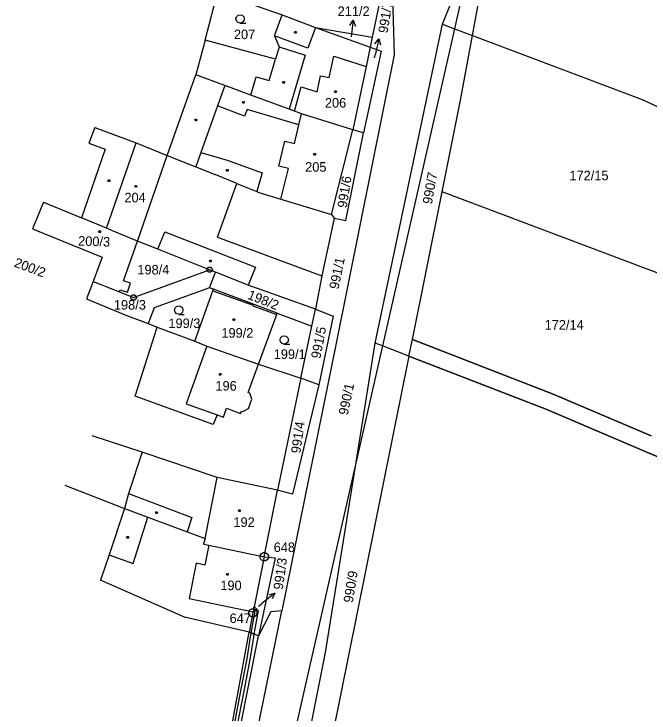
# Model space of a CAD drawing. Extents: x -755359 to -754474, y -1162585 to -1161655.
# Drawn here: x -755100.2 to -754987.3, y -1161900.8 to -1161776.6 of the extents above; entities that cross this region are included whole.
import ezdxf

# ---------------------------------------------------------------- set-up
doc = ezdxf.new("R2010")
doc.units = 0
for name, color, linetype in [('Vrstva 1', 7, 'Continuous'), ('Vrstva 12', 7, 'Continuous'), ('Vrstva 13', 7, 'Continuous'), ('Vrstva 2', 7, 'Continuous'), ('Vrstva 3', 7, 'Continuous'), ('Vrstva 4', 7, 'Continuous'), ('Vrstva 5', 7, 'Continuous'), ('Vrstva 7', 7, 'Continuous'), ('Vrstva 8', 7, 'Continuous')]:
    doc.layers.add(name, color=color, linetype=linetype)

msp = doc.modelspace()

# ---------------------------------------------------------------- linework, layer by layer
at = {"layer": 'Vrstva 1'}
for p, q in [((-755018.69, -1161780.44), (-755012.38, -1161745.91)), ((-755029.37, -1161746.66), (-755036.5, -1161780.73)), ((-755023.99, -1161778.44), (-755018.66, -1161765.05)), ((-755032.94, -1161771.83), (-755032.59, -1161783.86)), ((-755066.23, -1161781.24), (-755063.99, -1161772.75)), ((-755063.99, -1161772.75), (-755052.51, -1161776.75)), ((-755053.85, -1161780.46), (-755052.51, -1161776.75)), ((-755052.51, -1161776.75), (-755046.56, -1161779)), ((-755035.96, -1161835.09), (-755023.99, -1161778.44)), ((-755023.99, -1161778.44), (-755021.88, -1161779.23)), ((-755046.56, -1161779), (-755036.5, -1161780.73)), ((-755046.56, -1161779), (-755036.87, -1161782.52)), ((-755021.88, -1161779.23), (-755018.69, -1161780.44)), ((-755066.23, -1161781.24), (-755067.86, -1161787.41)), ((-755053.71, -1161784.66), (-755066.23, -1161781.24)), ((-755053.85, -1161780.46), (-755053.05, -1161782.42)), ((-755036.5, -1161780.73), (-755036.87, -1161782.52)), ((-755020.78, -1161791.91), (-755018.69, -1161780.44)), ((-755018.69, -1161780.44), (-754988.48, -1161791.81)), ((-755053.05, -1161782.42), (-755053.71, -1161784.66)), ((-755036.87, -1161782.52), (-755037.58, -1161785.91)), ((-755036.87, -1161782.52), (-755034.91, -1161783.19)), ((-755032.59, -1161783.86), (-755042.91, -1161835.1)), ((-755034.91, -1161783.19), (-755038.07, -1161797.72)), ((-755037.58, -1161785.91), (-755039.95, -1161797.18)), ((-755072.94, -1161801.75), (-755067.86, -1161787.41)), ((-755062.7, -1161789.31), (-755067.86, -1161787.41)), ((-755067.86, -1161787.41), (-755067.86, -1161787.41)), ((-755058.07, -1161791.01), (-755062.7, -1161789.31)), ((-755051.25, -1161793.52), (-755058.07, -1161791.01)), ((-755024.07, -1161808.23), (-755020.78, -1161791.91)), ((-754988.48, -1161791.81), (-754976.02, -1161797.59)), ((-755050.33, -1161793.86), (-755051.25, -1161793.52)), ((-755049.05, -1161794.33), (-755050.33, -1161793.86)), ((-755039.95, -1161797.18), (-755049.05, -1161794.33)), ((-755085.83, -1161796.77), (-755086.86, -1161799.58)), ((-755085.83, -1161796.77), (-755085.83, -1161796.77)), ((-755085.83, -1161796.77), (-755078.48, -1161799.49)), ((-755043.71, -1161812.24), (-755039.95, -1161797.18)), ((-755038.07, -1161797.72), (-755039.95, -1161797.18)), ((-755041.18, -1161813.33), (-755038.07, -1161797.72)), ((-755086.86, -1161799.58), (-755084.01, -1161800.63)), ((-755078.48, -1161799.49), (-755072.94, -1161801.75)), ((-755084.01, -1161800.63), (-755088.17, -1161812.84)), ((-755072.94, -1161801.75), (-755067.84, -1161803.8)), ((-755067.84, -1161803.8), (-755064.4, -1161805.16)), ((-755060.56, -1161806.72), (-755064.4, -1161805.16)), ((-755064, -1161816.28), (-755060.56, -1161806.72)), ((-755024.25, -1161809.12), (-755024.07, -1161808.23)), ((-754981.41, -1161824.3), (-755024.07, -1161808.23)), ((-755029.36, -1161834.44), (-755024.25, -1161809.12)), ((-755094.97, -1161810.07), (-755096.9, -1161814.81)), ((-755094.97, -1161810.07), (-755094.97, -1161810.07)), ((-755094.97, -1161810.07), (-755088.17, -1161812.84)), ((-755043.71, -1161812.24), (-755043.26, -1161812.92)), ((-755083.75, -1161814.68), (-755088.17, -1161812.84)), ((-755043.26, -1161812.92), (-755045.44, -1161823.16)), ((-755043.26, -1161812.92), (-755041.18, -1161813.33)), ((-755096.9, -1161814.81), (-755084.49, -1161819.84)), ((-755082.7, -1161815.12), (-755083.75, -1161814.68)), ((-755078.25, -1161816.98), (-755082.7, -1161815.12)), ((-755080.73, -1161824.02), (-755078.25, -1161816.98)), ((-755074.63, -1161818.41), (-755078.25, -1161816.98)), ((-755064, -1161816.28), (-755045.44, -1161823.16)), ((-755065.41, -1161822.06), (-755074.63, -1161818.41)), ((-755084.49, -1161819.84), (-755086.12, -1161824.14)), ((-755078.92, -1161826.99), (-755065.41, -1161822.06)), ((-755064.35, -1161822.48), (-755065.41, -1161822.06)), ((-755065.45, -1161825.27), (-755064.35, -1161822.48)), ((-755058.54, -1161824.78), (-755064.35, -1161822.48)), ((-755045.44, -1161823.16), (-755046.61, -1161829.09)), ((-755086.12, -1161824.14), (-755087.3, -1161827.26)), ((-755086.12, -1161824.14), (-755086.12, -1161824.14)), ((-755086.12, -1161824.14), (-755081.43, -1161826)), ((-755079.47, -1161824.46), (-755080.73, -1161824.02)), ((-755080, -1161826.07), (-755079.47, -1161824.46)), ((-755046.61, -1161829.09), (-755058.54, -1161824.78)), ((-755081.43, -1161826), (-755081.29, -1161825.61)), ((-755081.43, -1161826), (-755078.92, -1161826.99)), ((-755081.29, -1161825.61), (-755080, -1161826.07)), ((-755065.45, -1161825.27), (-755075.27, -1161828.85)), ((-755068.04, -1161834.73), (-755064.84, -1161825.82)), ((-755064.74, -1161825.54), (-755065.45, -1161825.27)), ((-755064.84, -1161825.82), (-755064.74, -1161825.54)), ((-755053.39, -1161829.8), (-755064.74, -1161825.54)), ((-755087.3, -1161827.26), (-755080.31, -1161830.13)), ((-755087.3, -1161827.26), (-755087.3, -1161827.26)), ((-755075.27, -1161828.85), (-755076.34, -1161831.64)), ((-755053.47, -1161830.02), (-755053.39, -1161829.8)), ((-755053.39, -1161829.8), (-755047.24, -1161832.11)), ((-755047.24, -1161832.11), (-755046.61, -1161829.09)), ((-755046.61, -1161829.09), (-755043.45, -1161830.32)), ((-755080.31, -1161830.13), (-755076.34, -1161831.64)), ((-755056.74, -1161838.86), (-755053.47, -1161830.02)), ((-755043.45, -1161830.32), (-755046.01, -1161842.53)), ((-755078.65, -1161844.52), (-755074.72, -1161832.26)), ((-755076.34, -1161831.64), (-755074.72, -1161832.26)), ((-755074.72, -1161832.26), (-755068.04, -1161834.73)), ((-755049.18, -1161841.35), (-755047.24, -1161832.11)), ((-755068.04, -1161834.73), (-755065.91, -1161835.63)), ((-755029.96, -1161837.42), (-755029.36, -1161834.44)), ((-755004.33, -1161844.15), (-755029.36, -1161834.44)), ((-755065.91, -1161835.63), (-755056.74, -1161838.86)), ((-755042.91, -1161835.1), (-755052.57, -1161882.7)), ((-755039.31, -1161855.89), (-755035.96, -1161835.09)), ((-755034.69, -1161835.58), (-755035.96, -1161835.09)), ((-755029.96, -1161837.42), (-755034.69, -1161835.58)), ((-755029.96, -1161837.42), (-755040.69, -1161890.6)), ((-755029.96, -1161837.42), (-755005.46, -1161846.93)), ((-755058.56, -1161843.89), (-755056.74, -1161838.86)), ((-755056.74, -1161838.86), (-755049.18, -1161841.35)), ((-755049.18, -1161841.35), (-755053.32, -1161861.22)), ((-755046.01, -1161842.53), (-755049.18, -1161841.35)), ((-755046.01, -1161842.53), (-755050.67, -1161861.93)), ((-755064.76, -1161849.59), (-755078.65, -1161844.52)), ((-755058.26, -1161844), (-755058.56, -1161843.89)), ((-755057.9, -1161845.09), (-755058.26, -1161844)), ((-754986.91, -1161851.57), (-755004.33, -1161844.15)), ((-755058.48, -1161846.72), (-755057.9, -1161845.09)), ((-755062.95, -1161848.24), (-755062.42, -1161846.64)), ((-755062.42, -1161846.64), (-755059.89, -1161847.61)), ((-755059.89, -1161847.61), (-755059.74, -1161847.19)), ((-755059.74, -1161847.19), (-755059.5, -1161847.27)), ((-755059.5, -1161847.27), (-755058.48, -1161846.72)), ((-755005.46, -1161846.93), (-754987.52, -1161854.57)), ((-755064.08, -1161847.84), (-755064.76, -1161849.59)), ((-755064.08, -1161847.84), (-755062.95, -1161848.24)), ((-755077.38, -1161854.48), (-755086.27, -1161851.57)), ((-755086.27, -1161851.57), (-755086.27, -1161851.57)), ((-755077.38, -1161854.48), (-755079.84, -1161861.83)), ((-755064.04, -1161858.98), (-755077.38, -1161854.48)), ((-754987.52, -1161854.57), (-754912.51, -1161886.53)), ((-755044.81, -1161890.11), (-755039.31, -1161855.89)), ((-755053.32, -1161861.22), (-755064.04, -1161858.98)), ((-755091.15, -1161860.37), (-755091.15, -1161860.37)), ((-755091.15, -1161860.37), (-755080.57, -1161864.47)), ((-755079.84, -1161861.83), (-755080.57, -1161864.47)), ((-755055.68, -1161873.06), (-755053.32, -1161861.22)), ((-755050.67, -1161861.93), (-755053.32, -1161861.22)), ((-755080.57, -1161864.47), (-755083.3, -1161872.73)), ((-755080.57, -1161864.47), (-755076.39, -1161866.02)), ((-755076.39, -1161866.02), (-755069.39, -1161868.63)), ((-755069.39, -1161868.63), (-755066.22, -1161869.81)), ((-755066.22, -1161869.81), (-755066.47, -1161870.86)), ((-755066.47, -1161870.86), (-755065.57, -1161871.04)), ((-755065.57, -1161871.04), (-755055.68, -1161873.06)), ((-755083.3, -1161872.73), (-755084.79, -1161877.24)), ((-755055.68, -1161873.06), (-755057.66, -1161882.87)), ((-755053.78, -1161873.28), (-755056.71, -1161887.12)), ((-755055.68, -1161873.06), (-755053.78, -1161873.28)), ((-755069.89, -1161883.79), (-755084.79, -1161877.24)), ((-755084.79, -1161877.24), (-755084.79, -1161877.24)), ((-755057.71, -1161883.06), (-755058.39, -1161886.49)), ((-755057.66, -1161882.87), (-755057.71, -1161883.06)), ((-755054.53, -1161882.87), (-755056.71, -1161887.12)), ((-755052.57, -1161882.7), (-755054.53, -1161882.87)), ((-755058.39, -1161886.49), (-755069.89, -1161883.79)), ((-755064.41, -1161919.47), (-755058.39, -1161886.49)), ((-755056.71, -1161887.12), (-755058.39, -1161886.49)), ((-755077.79, -1161993.12), (-755056.71, -1161887.12)), ((-755053.45, -1161933.51), (-755044.81, -1161890.11)), ((-755040.69, -1161890.6), (-755049.81, -1161934.92))]:
    msp.add_line(p, q, dxfattribs=at)
at = {"layer": 'Vrstva 12'}
for p, q in [((-755044.13, -1161787.9), (-755043.32, -1161784.1)), ((-755043.32, -1161784.1), (-755037.58, -1161785.91)), ((-755037.58, -1161785.91), (-755039.95, -1161797.18)), ((-755046.28, -1161790.43), (-755045.67, -1161787.57)), ((-755045.67, -1161787.57), (-755044.13, -1161787.9)), ((-755050.33, -1161793.86), (-755049.11, -1161789.56)), ((-755049.11, -1161789.56), (-755046.28, -1161790.43)), ((-755049.05, -1161794.33), (-755050.33, -1161793.86)), ((-755049.52, -1161796.33), (-755049.05, -1161794.33)), ((-755039.95, -1161797.18), (-755049.05, -1161794.33)), ((-755039.95, -1161797.18), (-755049.05, -1161794.33)), ((-755050.32, -1161799.64), (-755049.52, -1161796.33)), ((-755043.71, -1161812.24), (-755039.95, -1161797.18)), ((-755083.75, -1161814.68), (-755078.48, -1161799.49)), ((-755078.48, -1161799.49), (-755072.94, -1161801.75)), ((-755053.09, -1161803.64), (-755052.02, -1161799.21)), ((-755052.02, -1161799.21), (-755050.32, -1161799.64)), ((-755078.25, -1161816.98), (-755072.94, -1161801.75)), ((-755051.39, -1161804.05), (-755053.09, -1161803.64)), ((-755052.72, -1161809.52), (-755051.39, -1161804.05)), ((-755052.72, -1161809.52), (-755043.71, -1161812.24)), ((-755094.97, -1161810.07), (-755096.9, -1161814.81)), ((-755094.97, -1161810.07), (-755088.17, -1161812.84)), ((-755083.75, -1161814.68), (-755088.17, -1161812.84)), ((-755096.9, -1161814.81), (-755084.49, -1161819.84)), ((-755082.7, -1161815.12), (-755083.75, -1161814.68)), ((-755082.7, -1161815.12), (-755083.75, -1161814.68)), ((-755078.25, -1161816.98), (-755082.7, -1161815.12)), ((-755078.25, -1161816.98), (-755082.7, -1161815.12)), ((-755080.73, -1161824.02), (-755078.25, -1161816.98)), ((-755084.49, -1161819.84), (-755086.12, -1161824.14)), ((-755086.12, -1161824.14), (-755081.43, -1161826)), ((-755079.47, -1161824.46), (-755080.73, -1161824.02)), ((-755080, -1161826.07), (-755079.47, -1161824.46)), ((-755081.43, -1161826), (-755081.29, -1161825.61)), ((-755081.29, -1161825.61), (-755080, -1161826.07)), ((-755068.04, -1161834.73), (-755064.84, -1161825.82)), ((-755064.84, -1161825.82), (-755057.65, -1161828.38)), ((-755057.65, -1161828.38), (-755057.71, -1161828.5)), ((-755057.71, -1161828.5), (-755053.47, -1161830.02)), ((-755056.74, -1161838.86), (-755053.47, -1161830.02)), ((-755068.04, -1161834.73), (-755065.91, -1161835.63)), ((-755065.91, -1161835.63), (-755069.59, -1161845.88)), ((-755065.91, -1161835.63), (-755056.74, -1161838.86)), ((-755065.91, -1161835.63), (-755056.74, -1161838.86)), ((-755058.56, -1161843.89), (-755056.74, -1161838.86)), ((-755058.26, -1161844), (-755058.56, -1161843.89)), ((-755057.9, -1161845.09), (-755058.26, -1161844)), ((-755069.59, -1161845.88), (-755064.08, -1161847.84)), ((-755058.48, -1161846.72), (-755057.9, -1161845.09)), ((-755062.95, -1161848.24), (-755062.42, -1161846.64)), ((-755062.42, -1161846.64), (-755059.89, -1161847.61)), ((-755059.89, -1161847.61), (-755059.74, -1161847.19)), ((-755059.74, -1161847.19), (-755059.5, -1161847.27)), ((-755059.5, -1161847.27), (-755058.48, -1161846.72)), ((-755064.08, -1161847.84), (-755062.95, -1161848.24)), ((-755066.22, -1161869.81), (-755064.04, -1161858.98)), ((-755053.32, -1161861.22), (-755064.04, -1161858.98)), ((-755055.68, -1161873.06), (-755053.32, -1161861.22)), ((-755066.22, -1161869.81), (-755066.47, -1161870.86)), ((-755066.47, -1161870.86), (-755065.57, -1161871.04)), ((-755065.57, -1161871.04), (-755066.27, -1161874.54)), ((-755065.57, -1161871.04), (-755055.68, -1161873.06)), ((-755065.57, -1161871.04), (-755055.68, -1161873.06)), ((-755055.68, -1161873.06), (-755057.66, -1161882.87)), ((-755067.79, -1161874.23), (-755069.06, -1161880.5)), ((-755066.27, -1161874.54), (-755067.79, -1161874.23)), ((-755069.06, -1161880.5), (-755057.66, -1161882.87))]:
    msp.add_line(p, q, dxfattribs=at)
at = {"layer": 'Vrstva 13'}
for p, q in [((-755029.96, -1161837.42), (-755029.36, -1161834.44)), ((-755029.36, -1161834.44), (-755004.33, -1161844.15)), ((-755005.46, -1161846.93), (-755029.96, -1161837.42)), ((-755004.33, -1161844.15), (-754986.91, -1161851.57)), ((-754987.52, -1161854.57), (-755005.46, -1161846.93)), ((-754956.94, -1161867.6), (-754987.52, -1161854.57)), ((-755057.58, -1161882.48), (-755057.46, -1161881.89)), ((-755057.46, -1161881.89), (-755056.77, -1161882.61)), ((-755058.01, -1161886.63), (-755057.31, -1161882.77)), ((-755057.31, -1161882.77), (-755057.58, -1161882.48)), ((-755056.77, -1161882.61), (-755057.53, -1161886.81)), ((-755058.13, -1161887.3), (-755058.01, -1161886.63)), ((-755058.01, -1161886.63), (-755057.53, -1161886.81)), ((-755057.53, -1161886.81), (-755058.01, -1161886.63)), ((-755057.53, -1161886.81), (-755057.63, -1161887.38)), ((-755058.73, -1161891.23), (-755058.13, -1161887.3)), ((-755057.63, -1161887.38), (-755058.23, -1161891.31)), ((-755059.85, -1161896.89), (-755058.73, -1161891.23)), ((-755058.23, -1161891.31), (-755059.35, -1161896.99)), ((-755061.53, -1161905.62), (-755059.85, -1161896.89)), ((-755059.35, -1161896.99), (-755061.05, -1161905.72))]:
    msp.add_line(p, q, dxfattribs=at)
at = {"layer": 'Vrstva 3'}
for points in [[(-755059.97, -1161778.22), (-755060.35, -1161778.12), (-755060.62, -1161777.85), (-755060.72, -1161777.48), (-755060.62, -1161777.11), (-755060.35, -1161776.84), (-755059.98, -1161776.74), (-755059.61, -1161776.84), (-755059.34, -1161777.11), (-755059.24, -1161777.49), (-755059.34, -1161777.87), (-755059.61, -1161778.14), (-755059.99, -1161778.24), (-755058.99, -1161778.24)], [(-755070.89, -1161829.97), (-755071.27, -1161829.87), (-755071.54, -1161829.6), (-755071.64, -1161829.23), (-755071.54, -1161828.86), (-755071.27, -1161828.59), (-755070.9, -1161828.49), (-755070.53, -1161828.59), (-755070.26, -1161828.86), (-755070.16, -1161829.24), (-755070.26, -1161829.62), (-755070.53, -1161829.89), (-755070.91, -1161829.99), (-755069.91, -1161829.99)], [(-755052.13, -1161835.27), (-755052.51, -1161835.17), (-755052.78, -1161834.9), (-755052.88, -1161834.53), (-755052.78, -1161834.16), (-755052.51, -1161833.89), (-755052.14, -1161833.79), (-755051.77, -1161833.89), (-755051.5, -1161834.16), (-755051.4, -1161834.54), (-755051.5, -1161834.92), (-755051.77, -1161835.19), (-755052.15, -1161835.29), (-755051.15, -1161835.29)]]:
    msp.add_lwpolyline(points, dxfattribs=at)
at = {"layer": 'Vrstva 4'}
for p, q in [((-755018.66, -1161765.05), (-755021.88, -1161779.23)), ((-755046.56, -1161779), (-755047.94, -1161782.68)), ((-755021.88, -1161779.23), (-755034.69, -1161835.58)), ((-755047.94, -1161782.68), (-755053.85, -1161780.46)), ((-755053.05, -1161782.42), (-755048.44, -1161783.92)), ((-755054.84, -1161788.43), (-755053.71, -1161784.66)), ((-755048.44, -1161783.92), (-755051.25, -1161793.52)), ((-755044.13, -1161787.9), (-755043.32, -1161784.1)), ((-755043.32, -1161784.1), (-755037.58, -1161785.91)), ((-755046.28, -1161790.43), (-755045.67, -1161787.57)), ((-755045.67, -1161787.57), (-755044.13, -1161787.9)), ((-755058.07, -1161791.01), (-755057.11, -1161787.75)), ((-755057.11, -1161787.75), (-755054.84, -1161788.43)), ((-755062.7, -1161789.31), (-755064.01, -1161792.95)), ((-755050.33, -1161793.86), (-755049.11, -1161789.56)), ((-755049.11, -1161789.56), (-755046.28, -1161790.43)), ((-755064.01, -1161792.95), (-755066.99, -1161801.2)), ((-755059.19, -1161794.76), (-755064.01, -1161792.95)), ((-755058.74, -1161793.58), (-755059.19, -1161794.76)), ((-755049.52, -1161796.33), (-755058.74, -1161793.58)), ((-755049.52, -1161796.33), (-755049.05, -1161794.33)), ((-755050.32, -1161799.64), (-755049.52, -1161796.33)), ((-755083.75, -1161814.68), (-755078.48, -1161799.49)), ((-755053.09, -1161803.64), (-755052.02, -1161799.21)), ((-755052.02, -1161799.21), (-755050.32, -1161799.64)), ((-755066.99, -1161801.2), (-755067.84, -1161803.8)), ((-755066.99, -1161801.2), (-755062.31, -1161802.61)), ((-755078.25, -1161816.98), (-755072.94, -1161801.75)), ((-755062.31, -1161802.61), (-755056.07, -1161804.84)), ((-755051.39, -1161804.05), (-755053.09, -1161803.64)), ((-755056.07, -1161804.84), (-755056.99, -1161808.17)), ((-755052.72, -1161809.52), (-755051.39, -1161804.05)), ((-755060.56, -1161806.72), (-755056.99, -1161808.17)), ((-755056.99, -1161808.17), (-755056.63, -1161808.32)), ((-755056.63, -1161808.32), (-755052.72, -1161809.52)), ((-755052.72, -1161809.52), (-755043.71, -1161812.24)), ((-755074.63, -1161818.41), (-755073.38, -1161815.35)), ((-755073.38, -1161815.35), (-755057.25, -1161821.58)), ((-755057.25, -1161821.58), (-755058.54, -1161824.78)), ((-755064.84, -1161825.82), (-755057.65, -1161828.38)), ((-755057.65, -1161828.38), (-755057.71, -1161828.5)), ((-755057.71, -1161828.5), (-755053.47, -1161830.02)), ((-755065.91, -1161835.63), (-755069.59, -1161845.88)), ((-755034.69, -1161835.58), (-755039.31, -1161855.89)), ((-755069.59, -1161845.88), (-755064.08, -1161847.84)), ((-755039.31, -1161855.89), (-755061.51, -1161953.6)), ((-755066.22, -1161869.81), (-755064.04, -1161858.98)), ((-755079.84, -1161861.83), (-755068.56, -1161866.07)), ((-755079.03, -1161874.3), (-755076.39, -1161866.02)), ((-755068.56, -1161866.07), (-755069.39, -1161868.63)), ((-755065.57, -1161871.04), (-755066.27, -1161874.54)), ((-755083.3, -1161872.73), (-755079.03, -1161874.3)), ((-755067.79, -1161874.23), (-755069.06, -1161880.5)), ((-755066.27, -1161874.54), (-755067.79, -1161874.23)), ((-755069.06, -1161880.5), (-755057.66, -1161882.87)), ((-755067.04, -1161952.84), (-755052.57, -1161882.7))]:
    msp.add_line(p, q, dxfattribs=at)
at = {"layer": 'Vrstva 5'}
for points in [[(-755050.07, -1161779.71), (-755049.98, -1161779.86), (-755050.07, -1161780.01), (-755050.25, -1161780.01), (-755050.34, -1161779.86), (-755050.25, -1161779.71)], [(-755052.15, -1161788.59), (-755052.06, -1161788.74), (-755052.15, -1161788.89), (-755052.33, -1161788.89), (-755052.42, -1161788.74), (-755052.33, -1161788.59)], [(-755042.92, -1161790.24), (-755042.83, -1161790.39), (-755042.92, -1161790.54), (-755043.1, -1161790.54), (-755043.19, -1161790.39), (-755043.1, -1161790.24)], [(-755059.31, -1161792.17), (-755059.22, -1161792.32), (-755059.31, -1161792.47), (-755059.49, -1161792.47), (-755059.58, -1161792.32), (-755059.49, -1161792.17)], [(-755067.75, -1161795.32), (-755067.66, -1161795.47), (-755067.75, -1161795.62), (-755067.93, -1161795.62), (-755068.02, -1161795.47), (-755067.93, -1161795.32)], [(-755046.64, -1161801.41), (-755046.55, -1161801.56), (-755046.64, -1161801.71), (-755046.82, -1161801.71), (-755046.91, -1161801.56), (-755046.82, -1161801.41)], [(-755062.17, -1161804.27), (-755062.08, -1161804.42), (-755062.17, -1161804.57), (-755062.35, -1161804.57), (-755062.44, -1161804.42), (-755062.35, -1161804.27)], [(-755083.21, -1161806.06), (-755083.12, -1161806.21), (-755083.21, -1161806.36), (-755083.39, -1161806.36), (-755083.48, -1161806.21), (-755083.39, -1161806.06)], [(-755078.42, -1161807.06), (-755078.33, -1161807.21), (-755078.42, -1161807.36), (-755078.6, -1161807.36), (-755078.69, -1161807.21), (-755078.6, -1161807.06)], [(-755084.87, -1161815.15), (-755084.78, -1161815.3), (-755084.87, -1161815.45), (-755085.05, -1161815.45), (-755085.14, -1161815.3), (-755085.05, -1161815.15)], [(-755065.18, -1161820.38), (-755065.09, -1161820.53), (-755065.18, -1161820.68), (-755065.36, -1161820.68), (-755065.45, -1161820.53), (-755065.36, -1161820.38)], [(-755061, -1161830.8), (-755060.91, -1161830.95), (-755061, -1161831.1), (-755061.18, -1161831.1), (-755061.27, -1161830.95), (-755061.18, -1161830.8)], [(-755063.42, -1161840.49), (-755063.33, -1161840.64), (-755063.42, -1161840.79), (-755063.6, -1161840.79), (-755063.69, -1161840.64), (-755063.6, -1161840.49)], [(-755074.76, -1161865.1), (-755074.67, -1161865.25), (-755074.76, -1161865.4), (-755074.94, -1161865.4), (-755075.03, -1161865.25), (-755074.94, -1161865.1)], [(-755060.03, -1161864.71), (-755059.94, -1161864.86), (-755060.03, -1161865.01), (-755060.21, -1161865.01), (-755060.3, -1161864.86), (-755060.21, -1161864.71)], [(-755079.89, -1161869.46), (-755079.8, -1161869.61), (-755079.89, -1161869.76), (-755080.07, -1161869.76), (-755080.16, -1161869.61), (-755080.07, -1161869.46)], [(-755062.16, -1161876.05), (-755062.07, -1161876.2), (-755062.16, -1161876.35), (-755062.34, -1161876.35), (-755062.43, -1161876.2), (-755062.34, -1161876.05)]]:
    msp.add_lwpolyline(points, close=True, dxfattribs=at)
at = {"layer": 'Vrstva 7'}
for p, q in [((-755039.855, -1161777.706), (-755040.25, -1161780.68)), ((-755035.294, -1161781.027), (-755035.97, -1161783.95)), ((-755036.07, -1161784.37), (-755035.97, -1161783.95)), ((-755053.798, -1161879.522), (-755056.13, -1161881.41)), ((-755056.69, -1161881.86), (-755056.13, -1161881.41))]:
    msp.add_line(p, q, dxfattribs=at)
for points in [[(-755040.482, -1161778.632), (-755039.855, -1161777.706), (-755039.491, -1161778.763)], [(-755036.007, -1161781.889), (-755035.294, -1161781.027), (-755035.032, -1161782.114)], [(-755054.89, -1161879.763), (-755053.798, -1161879.522), (-755054.261, -1161880.54)]]:
    msp.add_lwpolyline(points, dxfattribs=at)
at = {"layer": 'Vrstva 8'}
for p, q in [((-755065.53, -1161822.06), (-755065.29, -1161822.06)), ((-755079.04, -1161826.99), (-755078.8, -1161826.99)), ((-755055.73, -1161873.06), (-755055.63, -1161873.06)), ((-755057.76, -1161883.06), (-755057.66, -1161883.06))]:
    msp.add_line(p, q, dxfattribs=at)
for points in [[(-755065.26, -1161821.58), (-755065.01, -1161821.76), (-755064.91, -1161822.05), (-755065.01, -1161822.34), (-755065.26, -1161822.52), (-755065.57, -1161822.52), (-755065.82, -1161822.34), (-755065.92, -1161822.05), (-755065.82, -1161821.76), (-755065.57, -1161821.58)], [(-755078.77, -1161826.51), (-755078.52, -1161826.69), (-755078.42, -1161826.98), (-755078.52, -1161827.27), (-755078.77, -1161827.45), (-755079.08, -1161827.45), (-755079.33, -1161827.27), (-755079.43, -1161826.98), (-755079.33, -1161826.69), (-755079.08, -1161826.51)], [(-755055.49, -1161872.34), (-755055.15, -1161872.53), (-755054.96, -1161872.87), (-755054.96, -1161873.26), (-755055.15, -1161873.6), (-755055.49, -1161873.79), (-755055.88, -1161873.79), (-755056.22, -1161873.6), (-755056.41, -1161873.26), (-755056.41, -1161872.87), (-755056.22, -1161872.53), (-755055.88, -1161872.34)], [(-755057.52, -1161882.34), (-755057.18, -1161882.53), (-755056.99, -1161882.87), (-755056.99, -1161883.26), (-755057.18, -1161883.6), (-755057.52, -1161883.79), (-755057.91, -1161883.79), (-755058.25, -1161883.6), (-755058.44, -1161883.26), (-755058.44, -1161882.87), (-755058.25, -1161882.53), (-755057.91, -1161882.34)]]:
    msp.add_lwpolyline(points, close=True, dxfattribs=at)

# ---------------------------------------------------------------- texts
at = {"layer": 'Vrstva 2'}
for s, height, p in [('207', 1.7, (-755061.093, -1161781.08)), ('211/2', 0.1, (-755040.236, -1161780.68)), ('991/7', 0.1, (-755036.056, -1161784.37)), ('206', 1.7, (-755044.913, -1161793.25)), ('205', 1.7, (-755048.423, -1161804.64)), ('172/15', 1.7, (-755001.427, -1161806.16)), ('204', 1.7, (-755080.563, -1161810.08)), ('198/4', 1.7, (-755078.262, -1161822.9)), ('198/3', 1.7, (-755082.429, -1161829.15)), ('199/3', 1.7, (-755072.737, -1161832.43)), ('172/14', 1.7, (-755005.84, -1161832.7)), ('199/2', 1.7, (-755063.317, -1161834.14)), ('199/1', 1.7, (-755054.017, -1161837.92)), ('196', 1.7, (-755064.377, -1161843.54)), ('192', 1.7, (-755061.177, -1161867.77)), ('190', 1.7, (-755063.507, -1161879.01)), ('991/3', 0.1, (-755056.676, -1161881.86))]:
    msp.add_text(s, height=height, dxfattribs=at).set_placement(p)
for s, rotation, p in [('990/7', 80.0995, (-755025.889, -1161810.506)), ('991/6', 81.01623, (-755041.043, -1161811.166)), ('200/3', 357.92673, (-755088.815, -1161817.758)), ('200/2', 339.53479, (-755100.305, -1161821.469)), ('991/1', 78.32333, (-755042.502, -1161825.628)), ('198/2', 338.38888, (-755058.805, -1161827.175)), ('991/5', 79.18277, (-755045.725, -1161837.957)), ('990/1', 78.32333, (-755040.842, -1161847.998)), ('991/4', 81.87567, (-755049.286, -1161854.795)), ('990/9', 81.01623, (-755039.943, -1161881.336))]:
    msp.add_text(s, height=1.7, rotation=rotation, dxfattribs=at).set_placement(p)
at = {"layer": 'Vrstva 7'}
msp.add_text('211/2', height=1.7, dxfattribs=at).set_placement((-755042.644, -1161776.96))
for s, rotation, p in [('991/7', 81.01623, (-755033.773, -1161780.106)), ('991/3', 81.99026, (-755052.417, -1161879.025))]:
    msp.add_text(s, height=1.7, rotation=rotation, dxfattribs=at).set_placement(p)
at = {"layer": 'Vrstva 8'}
for s, p in [('648', (-755054.023, -1161872.23)), ('647', (-755061.853, -1161884.85))]:
    msp.add_text(s, height=1.7, dxfattribs=at).set_placement(p)

doc.saveas('drawing.dxf')
